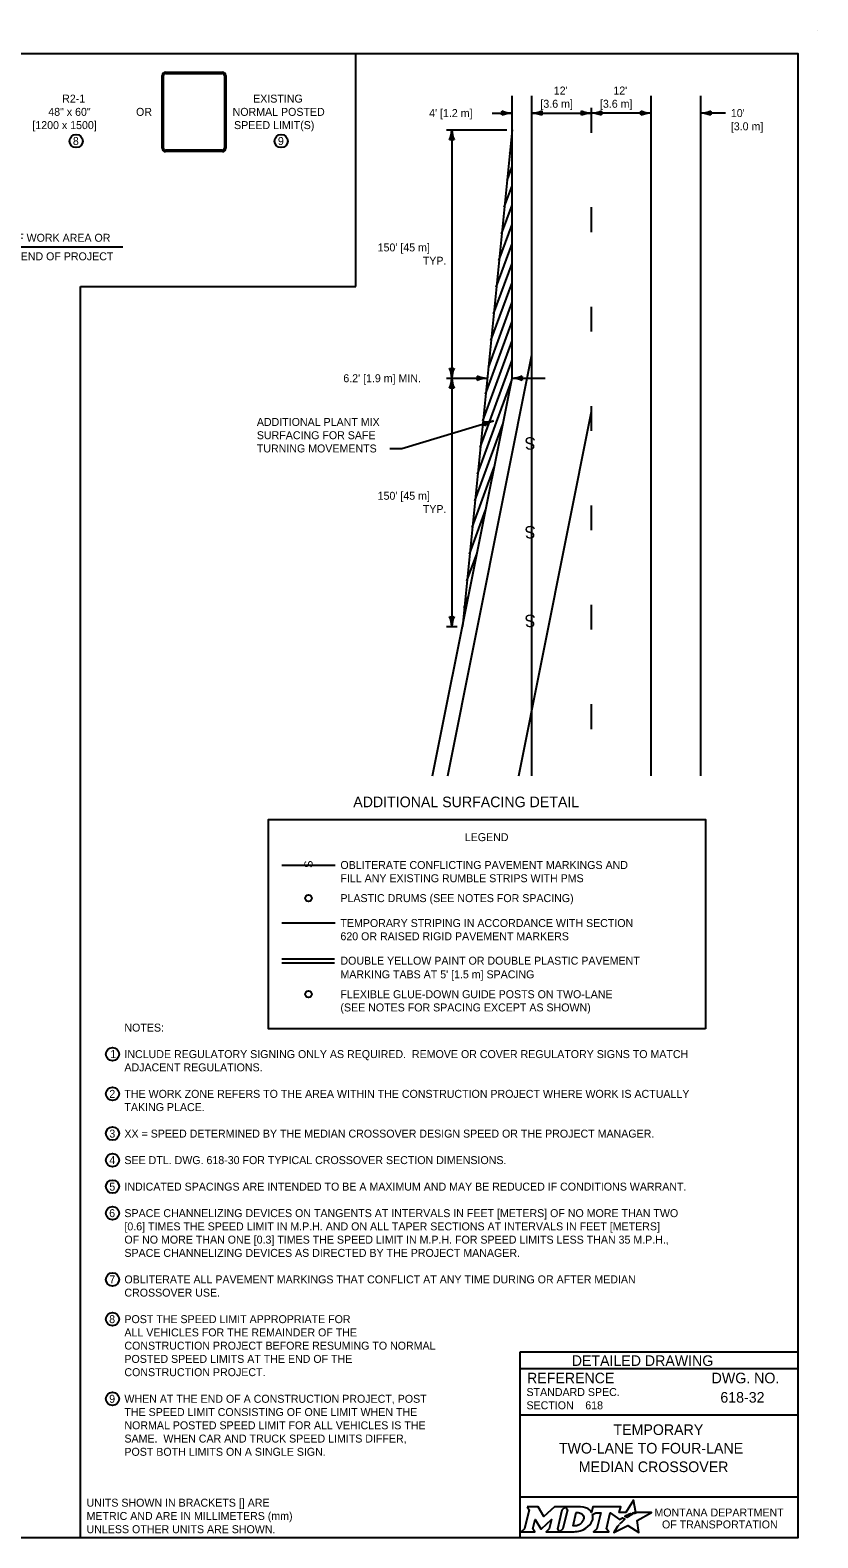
# Model space of a CAD drawing. Extents: x 49991.4 to 50021, y 49987.6 to 50011.4.
# Drawn here: x 50010.95 to 50016.9, y 49987.8 to 49999.18 of the extents above; entities that cross this region are included whole.
import ezdxf

# ---------------------------------------------------------------- set-up
doc = ezdxf.new("R2010")
doc.units = 0
for name, color, linetype in [('Default', 7, 'Continuous'), ('Level 1', 7, 'Continuous'), ('Level 2', 7, 'Continuous'), ('Level 3', 7, 'Continuous'), ('Level 5', 7, 'Continuous')]:
    doc.layers.add(name, color=color, linetype=linetype)

msp = doc.modelspace()

# ---------------------------------------------------------------- linework, layer by layer
at = {"layer": 'Default'}
for points in [[(50015.513, 49987.981), (50015.502, 49987.987), (50015.514, 49987.99), (50015.526, 49987.991), (50015.508, 49988.082), (50015.449, 49987.99), (50015.401, 49987.99), (50015.412, 49988.034), (50015.202, 49988.034), (50015.192, 49987.991), (50015.186, 49988)], [(50014.706, 49988.034), (50014.72, 49988.01), (50014.686, 49987.867), (50014.66, 49987.845), (50014.762, 49987.845), (50014.749, 49987.867), (50014.765, 49987.937), (50014.809, 49987.868), (50014.814, 49987.868), (50014.889, 49987.938), (50014.872, 49987.867), (50014.848, 49987.845), (50014.949, 49987.845), (50014.936, 49987.868), (50014.969, 49988.011)], [(50014.969, 49988.011), (50014.994, 49988.034), (50014.912, 49988.034), (50014.832, 49987.961), (50014.788, 49988.034), (50014.706, 49988.034)], [(50015.108, 49988.034), (50014.994, 49988.034), (50015.009, 49988.011), (50014.975, 49987.867), (50014.949, 49987.845), (50015.06, 49987.845)], [(50015.132, 49987.947), (50015.13, 49987.939), (50015.127, 49987.93), (50015.123, 49987.922), (50015.118, 49987.914), (50015.111, 49987.907), (50015.103, 49987.901), (50015.095, 49987.896), (50015.086, 49987.892), (50015.077, 49987.89), (50015.067, 49987.889), (50015.052, 49987.889), (50015.075, 49987.989), (50015.091, 49987.989), (50015.099, 49987.988), (50015.106, 49987.986), (50015.113, 49987.983), (50015.119, 49987.979), (50015.124, 49987.974), (50015.128, 49987.968), (50015.13, 49987.962), (50015.132, 49987.955), (50015.132, 49987.952), (50015.132, 49987.947)], [(50015.199, 49987.975), (50015.224, 49987.988), (50015.261, 49987.988), (50015.232, 49987.867), (50015.205, 49987.845), (50015.321, 49987.845), (50015.304, 49987.867), (50015.332, 49987.988), (50015.403, 49987.936), (50015.424, 49987.951), (50015.444, 49987.94)], [(50015.388, 49987.884), (50015.373, 49987.86), (50015.368, 49987.852), (50015.362, 49987.844), (50015.36, 49987.839), (50015.465, 49987.893), (50015.549, 49987.838), (50015.536, 49987.93), (50015.643, 49987.989), (50015.594, 49987.989), (50015.564, 49987.99), (50015.543, 49987.99), (50015.536, 49987.989), (50015.531, 49987.987), (50015.523, 49987.985), (50015.513, 49987.981)], [(50015.462, 49987.954), (50015.46, 49987.952), (50015.442, 49987.961), (50015.452, 49987.967), (50015.456, 49987.969), (50015.465, 49987.973), (50015.47, 49987.976), (50015.478, 49987.979), (50015.485, 49987.982), (50015.497, 49987.974), (50015.493, 49987.972), (50015.489, 49987.97), (50015.484, 49987.967), (50015.479, 49987.965), (50015.478, 49987.963), (50015.475, 49987.962), (50015.472, 49987.96), (50015.47, 49987.959), (50015.467, 49987.957), (50015.465, 49987.955), (50015.462, 49987.954)], [(50015.106, 49987.852), (50015.114, 49987.855), (50015.127, 49987.86), (50015.148, 49987.871)], [(50015.402, 49987.9), (50015.402, 49987.9)]]:
    msp.add_lwpolyline(points, dxfattribs=at)
for centre, radius, start, end in [((50015.087, 49987.973), 0.118, 300.9103, 339.1383), ((50015.131, 49987.955), 0.0709, 339.5329, 15.8582)]:
    msp.add_arc(centre, radius, start, end, dxfattribs=at)
for centre, major_axis, ratio, start_param, end_param in [((50015.106, 49987.986), (0.0834, -0.0037), 0.568097, 0.61298, 1.570796), ((50015.161, 49987.994), (0.0361, -0.0295), 0.469099, 1.225588, 1.570796), ((50015.433, 49987.93), (-0.0112, -0.0097), 0.021651, 3.157348, 6.283185), ((50015.06, 49987.993), (0, 0.148), 0.987302, 3.139398, 3.456847), ((50015.395, 49987.892), (-0.00694, -0.00806), 0.008222, 0, 3.137361), ((50015.412, 49987.911), (-0.0098, -0.0102), 0.016458, 3.141593, 6.279097)]:
    msp.add_ellipse(centre, major_axis=major_axis, ratio=ratio, start_param=start_param, end_param=end_param, dxfattribs=at)
at = {"layer": 'Level 1'}
for p, q in [((50016.9, 49999.176), (50016.9, 49999.176)), ((50011.974, 49998.859), (50012.404, 49998.859)), ((50011.974, 49998.849), (50012.404, 49998.849)), ((50011.949, 49998.284), (50011.949, 49998.834)), ((50011.959, 49998.284), (50011.959, 49998.834)), ((50012.419, 49998.834), (50012.419, 49998.284)), ((50012.429, 49998.834), (50012.429, 49998.284)), ((50014.591, 49996.549), (50014.591, 49998.68)), ((50014.741, 49996.726), (50014.741, 49998.68)), ((50015.641, 49993.549), (50015.641, 49998.68)), ((50016.016, 49993.549), (50016.016, 49998.68)), ((50015.191, 49998.402), (50015.191, 49998.589)), ((50014.591, 49998.423), (50014.216, 49994.675)), ((50014.573, 49998.244), (50014.591, 49998.293)), ((50012.404, 49998.269), (50011.974, 49998.269)), ((50012.404, 49998.259), (50011.974, 49998.259)), ((50014.553, 49998.042), (50014.591, 49998.147)), ((50014.532, 49997.841), (50014.591, 49998.001)), ((50014.512, 49997.639), (50014.591, 49997.855)), ((50015.191, 49997.652), (50015.191, 49997.839)), ((50014.492, 49997.438), (50014.591, 49997.708)), ((50014.472, 49997.236), (50014.591, 49997.562)), ((50014.452, 49997.034), (50014.591, 49997.416)), ((50014.432, 49996.833), (50014.591, 49997.27)), ((50014.412, 49996.631), (50014.591, 49997.124)), ((50015.191, 49996.902), (50015.191, 49997.089)), ((50014.391, 49996.43), (50014.591, 49996.977)), ((50014.371, 49996.228), (50014.591, 49996.831)), ((50014.105, 49993.549), (50014.741, 49996.726)), ((50014.741, 49994.049), (50014.741, 49996.726)), ((50014.351, 49996.027), (50014.591, 49996.685)), ((50013.991, 49993.549), (50014.591, 49996.549)), ((50014.331, 49995.825), (50014.586, 49996.526)), ((50014.641, 49993.549), (50015.191, 49996.299)), ((50015.191, 49996.152), (50015.191, 49996.339)), ((50014.311, 49995.624), (50014.521, 49996.202)), ((50014.291, 49995.422), (50014.456, 49995.877)), ((50014.27, 49995.221), (50014.391, 49995.553)), ((50015.191, 49995.402), (50015.191, 49995.589)), ((50014.25, 49995.019), (50014.327, 49995.229)), ((50014.23, 49994.817), (50014.262, 49994.904)), ((50015.191, 49994.652), (50015.191, 49994.839)), ((50015.191, 49993.902), (50015.191, 49994.089)), ((50014.741, 49993.549), (50014.741, 49994.049)), ((50013.255, 49992.873), (50012.853, 49992.873)), ((50013.255, 49992.438), (50012.853, 49992.438)), ((50013.251, 49992.165), (50012.853, 49992.165)), ((50013.251, 49992.135), (50012.853, 49992.135))]:
    msp.add_line(p, q, dxfattribs=at)
msp.add_lwpolyline([(49999.384, 49998.999), (50016.75, 49998.999), (50016.75, 49987.799), (49999.384, 49987.799)], close=True, dxfattribs=at)
for centre in [(50013.054, 49992.626), (50013.054, 49991.901)]:
    msp.add_circle(centre, 0.025, dxfattribs=at)
for centre, radius, start, end in [((50011.974, 49998.834), 0.025, 90, 180), ((50011.974, 49998.834), 0.015, 90, 180), ((50012.404, 49998.834), 0.025, 0, 90), ((50012.404, 49998.834), 0.015, 0, 90), ((50011.974, 49998.284), 0.025, 180, 270), ((50011.974, 49998.284), 0.015, 180, 270), ((50012.404, 49998.284), 0.025, 270, 0), ((50012.404, 49998.284), 0.015, 270, 0)]:
    msp.add_arc(centre, radius, start, end, dxfattribs=at)
at = {"layer": 'Level 2'}
msp.add_lwpolyline([(50016.051, 49991.64), (50012.753, 49991.64), (50012.753, 49993.22), (50016.051, 49993.22)], close=True, dxfattribs=at)
for centre in [(50011.3, 49998.339), (50012.848, 49998.339), (50011.574, 49991.449), (50011.574, 49991.149), (50011.574, 49990.849), (50011.574, 49990.649), (50011.574, 49990.449), (50011.574, 49990.249), (50011.574, 49989.749), (50011.574, 49989.449), (50011.574, 49988.848)]:
    msp.add_circle(centre, 0.05, dxfattribs=at)
at = {"layer": 'Level 3'}
for p, q in [((50013.411, 49997.242), (50013.411, 49998.999)), ((50014.441, 49998.55), (50014.591, 49998.55)), ((50014.741, 49998.55), (50015.191, 49998.55)), ((50015.641, 49998.55), (50015.191, 49998.55)), ((50016.203, 49998.55), (50016.016, 49998.55)), ((50014.096, 49998.423), (50014.551, 49998.423)), ((50014.136, 49998.423), (50014.136, 49996.549)), ((50011.652, 49997.539), (50008.697, 49997.539)), ((50011.332, 49987.799), (50011.332, 49997.242)), ((50011.332, 49997.242), (50013.411, 49997.242)), ((50014.096, 49996.549), (50014.403, 49996.549)), ((50014.136, 49996.549), (50014.136, 49994.675)), ((50014.591, 49996.549), (50014.841, 49996.549)), ((50013.758, 49996.019), (50014.451, 49996.228)), ((50013.667, 49996.019), (50013.758, 49996.019)), ((50014.096, 49994.675), (50014.176, 49994.675))]:
    msp.add_line(p, q, dxfattribs=at)
for centre, radius, start, end in [((50014.6, 49998.772), 0.222, 247.456, 267.6395), ((50014.462, 49998.55), 0.0548, 342.1388, 17.8612), ((50014.602, 49998.317), 0.233, 92.8273, 112.0772), ((50014.729, 49998.782), 0.233, 272.8273, 292.0772), ((50014.731, 49998.328), 0.222, 67.456, 87.6395), ((50014.869, 49998.55), 0.0548, 162.1388, 197.8612), ((50015.2, 49998.772), 0.222, 247.456, 267.6395), ((50015.062, 49998.55), 0.0548, 342.1388, 17.8612), ((50015.202, 49998.317), 0.233, 92.8273, 112.0772), ((50015.179, 49998.782), 0.233, 272.8273, 292.0772), ((50015.181, 49998.328), 0.222, 67.456, 87.6395), ((50015.319, 49998.55), 0.0548, 162.1388, 197.8612), ((50015.65, 49998.772), 0.222, 247.456, 267.6395), ((50015.512, 49998.55), 0.0548, 342.1388, 17.8612), ((50015.652, 49998.317), 0.233, 92.8273, 112.0772), ((50016.004, 49998.782), 0.233, 272.8273, 292.0772), ((50016.006, 49998.328), 0.222, 67.456, 87.6395), ((50016.144, 49998.55), 0.0548, 162.1388, 197.8612), ((50013.914, 49998.432), 0.222, 337.456, 357.6395), ((50014.369, 49998.435), 0.233, 182.8273, 202.0772), ((50014.136, 49998.295), 0.0548, 72.1388, 107.8612), ((50014.136, 49996.677), 0.0548, 252.1388, 287.8612), ((50013.903, 49996.538), 0.233, 2.8273, 22.0772), ((50014.358, 49996.54), 0.222, 157.456, 177.6395), ((50013.914, 49996.558), 0.222, 337.456, 357.6395), ((50014.136, 49996.421), 0.0548, 72.1388, 107.8612), ((50014.369, 49996.561), 0.233, 182.8273, 202.0772), ((50014.412, 49996.771), 0.222, 247.456, 267.6395), ((50014.275, 49996.549), 0.0548, 342.1388, 17.8612), ((50014.415, 49996.316), 0.233, 92.8273, 112.0772), ((50014.579, 49996.782), 0.233, 272.8273, 292.0772), ((50014.581, 49996.327), 0.222, 67.456, 87.6395), ((50014.719, 49996.549), 0.0548, 162.1388, 197.8612), ((50014.394, 49996.443), 0.222, 264.5994, 284.7829), ((50014.328, 49996.19), 0.0548, 359.2822, 35.0045), ((50014.53, 49996.009), 0.233, 109.9707, 129.2205), ((50014.136, 49994.803), 0.0548, 252.1388, 287.8612), ((50013.903, 49994.664), 0.233, 2.8273, 22.0772), ((50014.358, 49994.666), 0.222, 157.456, 177.6395)]:
    msp.add_arc(centre, radius, start, end, dxfattribs=at)
at = {"layer": 'Level 5'}
for p, q in [((50016.75, 49989.199), (50014.65, 49989.199)), ((50014.65, 49989.199), (50014.65, 49987.799)), ((50016.75, 49989.074), (50014.65, 49989.074)), ((50016.386, 49988.859), (50016.386, 49988.859)), ((50016.75, 49988.724), (50014.65, 49988.724)), ((50015.144, 49988.799), (50015.144, 49988.799)), ((50015.7, 49988.475), (50015.7, 49988.475)), ((50016.75, 49988.106), (50014.65, 49988.106))]:
    msp.add_line(p, q, dxfattribs=at)

# ---------------------------------------------------------------- texts
at = {"layer": 'Default'}
for s, p in [('MONTANA DEPARTMENT', (50015.666, 49987.96)), ('OF TRANSPORTATION', (50015.723, 49987.87))]:
    msp.add_text(s, height=0.06, dxfattribs=at).set_placement(p)
at = {"layer": 'Level 1'}
for height, rotation, p in [(0.0937, 180, (50014.77, 49996.104)), (0.0937, 180, (50014.77, 49995.434)), (0.0937, 180, (50014.77, 49994.765)), (0.0625, 90, (50013.085, 49992.854))]:
    msp.add_text('S', height=height, rotation=rotation, dxfattribs=at).set_placement(p)
at = {"layer": 'Level 2'}
for s, height, p in [("12'", 0.06, (50014.906, 49998.69)), ("12'", 0.06, (50015.356, 49998.69)), ('R2-1', 0.06, (50011.194, 49998.629)), ('EXISTING', 0.06, (50012.636, 49998.629)), ('[3.6 m]', 0.06, (50014.805, 49998.59)), ('[3.6 m]', 0.06, (50015.255, 49998.59)), ('48" x 60"', 0.06, (50011.089, 49998.529)), ('OR', 0.06, (50011.752, 49998.529)), ('NORMAL POSTED', 0.06, (50012.481, 49998.529)), ("4' [1.2 m]", 0.06, (50013.965, 49998.52)), ("10' ", 0.06, (50016.243, 49998.52)), ('[1200 x 1500]', 0.06, (50010.969, 49998.429)), ('SPEED LIMIT(S)', 0.06, (50012.492, 49998.429)), ('[3.0 m]', 0.06, (50016.243, 49998.42)), ('8', 0.06, (50011.275, 49998.309)), ('9', 0.06, (50012.823, 49998.309)), ('END OF WORK AREA OR', 0.06, (50010.6, 49997.579)), ('END OF PROJECT', 0.06, (50010.881, 49997.439)), ("150' [45 m]", 0.06, (50013.576, 49997.506)), ('TYP.', 0.06, (50013.917, 49997.406)), ("6.2' [1.9 m] MIN.", 0.06, (50013.317, 49996.519)), ('ADDITIONAL PLANT MIX ', 0.06, (50012.664, 49996.189)), ('SURFACING FOR SAFE ', 0.06, (50012.664, 49996.089)), ('TURNING MOVEMENTS', 0.06, (50012.664, 49995.989)), ("150' [45 m]", 0.06, (50013.576, 49995.632)), ('TYP.', 0.06, (50013.917, 49995.532)), ('ADDITIONAL SURFACING DETAIL', 0.08, (50013.392, 49993.312)), ('LEGEND', 0.06, (50014.234, 49993.056)), ('OBLITERATE CONFLICTING PAVEMENT MARKINGS AND', 0.06, (50013.295, 49992.846)), ('FILL ANY EXISTING RUMBLE STRIPS WITH PMS', 0.06, (50013.295, 49992.746)), ('PLASTIC DRUMS (SEE NOTES FOR SPACING)', 0.06, (50013.295, 49992.596)), ('TEMPORARY STRIPING IN ACCORDANCE WITH SECTION ', 0.06, (50013.295, 49992.408)), ('620 OR RAISED RIGID PAVEMENT MARKERS', 0.06, (50013.295, 49992.308)), ('DOUBLE YELLOW PAINT OR DOUBLE PLASTIC PAVEMENT', 0.06, (50013.295, 49992.124)), ("MARKING TABS AT 5' [1.5 m] SPACING", 0.06, (50013.295, 49992.021)), ('FLEXIBLE GLUE-DOWN GUIDE POSTS ON TWO-LANE', 0.06, (50013.295, 49991.871)), ('(SEE NOTES FOR SPACING EXCEPT AS SHOWN)', 0.06, (50013.295, 49991.771)), ('NOTES:', 0.06, (50011.664, 49991.619)), ('1', 0.06, (50011.557, 49991.419)), ('INCLUDE REGULATORY SIGNING ONLY AS REQUIRED.  REMOVE OR COVER REGULATORY SIGNS TO MATCH ', 0.06, (50011.664, 49991.419)), ('ADJACENT REGULATIONS.', 0.06, (50011.664, 49991.319)), ('2', 0.06, (50011.55, 49991.119)), ('THE WORK ZONE REFERS TO THE AREA WITHIN THE CONSTRUCTION PROJECT WHERE WORK IS ACTUALLY ', 0.06, (50011.664, 49991.119)), ('TAKING PLACE.', 0.06, (50011.664, 49991.019)), ('3', 0.06, (50011.55, 49990.819)), ('XX = SPEED DETERMINED BY THE MEDIAN CROSSOVER DESIGN SPEED OR THE PROJECT MANAGER.', 0.06, (50011.664, 49990.819)), ('4', 0.06, (50011.55, 49990.619)), ('SEE DTL. DWG. 618-30 FOR TYPICAL CROSSOVER SECTION DIMENSIONS.', 0.06, (50011.664, 49990.619)), ('5', 0.06, (50011.55, 49990.419)), ('INDICATED SPACINGS ARE INTENDED TO BE A MAXIMUM AND MAY BE REDUCED IF CONDITIONS WARRANT.', 0.06, (50011.664, 49990.419)), ('6', 0.06, (50011.549, 49990.219)), ('SPACE CHANNELIZING DEVICES ON TANGENTS AT INTERVALS IN FEET [METERS] OF NO MORE THAN TWO  ', 0.06, (50011.664, 49990.219)), ('[0.6] TIMES THE SPEED LIMIT IN M.P.H. AND ON ALL TAPER SECTIONS AT INTERVALS IN FEET [METERS] ', 0.06, (50011.664, 49990.119)), ('OF NO MORE THAN ONE [0.3] TIMES THE SPEED LIMIT IN M.P.H. FOR SPEED LIMITS LESS THAN 35 M.P.H., ', 0.06, (50011.664, 49990.019)), ('SPACE CHANNELIZING DEVICES AS DIRECTED BY THE PROJECT MANAGER.', 0.06, (50011.664, 49989.919)), ('7', 0.06, (50011.55, 49989.719)), ('OBLITERATE ALL PAVEMENT MARKINGS THAT CONFLICT AT ANY TIME DURING OR AFTER MEDIAN ', 0.06, (50011.664, 49989.719)), ('CROSSOVER USE. ', 0.06, (50011.664, 49989.619)), ('8', 0.06, (50011.549, 49989.419)), ('POST THE SPEED LIMIT APPROPRIATE FOR ', 0.06, (50011.664, 49989.419)), ('ALL VEHICLES FOR THE REMAINDER OF THE ', 0.06, (50011.664, 49989.319)), ('CONSTRUCTION PROJECT BEFORE RESUMING TO NORMAL', 0.06, (50011.664, 49989.219)), ('POSTED SPEED LIMITS AT THE END OF THE ', 0.06, (50011.664, 49989.119)), ('CONSTRUCTION PROJECT.', 0.06, (50011.664, 49989.019)), ('9', 0.06, (50011.549, 49988.818)), ('WHEN AT THE END OF A CONSTRUCTION PROJECT, POST', 0.06, (50011.664, 49988.818)), ('618-32', 0.08, (50016.164, 49988.819)), ('THE SPEED LIMIT CONSISTING OF ONE LIMIT WHEN THE', 0.06, (50011.664, 49988.718)), ('618', 0.06, (50015.144, 49988.769)), ('NORMAL POSTED SPEED LIMIT FOR ALL VEHICLES IS THE ', 0.06, (50011.664, 49988.618)), ('TEMPORARY', 0.08, (50015.357, 49988.575)), ('SAME.  WHEN CAR AND TRUCK SPEED LIMITS DIFFER, ', 0.06, (50011.664, 49988.518)), ('TWO-LANE TO FOUR-LANE', 0.08, (50014.945, 49988.435)), ('POST BOTH LIMITS ON A SINGLE SIGN.', 0.06, (50011.664, 49988.418)), ('MEDIAN CROSSOVER', 0.08, (50015.095, 49988.295)), ('UNITS SHOWN IN BRACKETS [] ARE ', 0.06, (50011.378, 49988.034)), ('METRIC AND ARE IN MILLIMETERS (mm) ', 0.06, (50011.378, 49987.934)), ('UNLESS OTHER UNITS ARE SHOWN.', 0.06, (50011.378, 49987.834))]:
    msp.add_text(s, height=height, dxfattribs=at).set_placement(p)
at = {"layer": 'Level 5'}
for s, height, p in [('DETAILED DRAWING', 0.0799, (50015.042, 49989.096)), ('REFERENCE', 0.08, (50014.704, 49988.965)), ('DWG. NO.', 0.08, (50016.098, 49988.965)), ('STANDARD SPEC.', 0.06, (50014.7, 49988.869)), ('SECTION', 0.06, (50014.7, 49988.769))]:
    msp.add_text(s, height=height, dxfattribs=at).set_placement(p)

doc.saveas('drawing.dxf')
